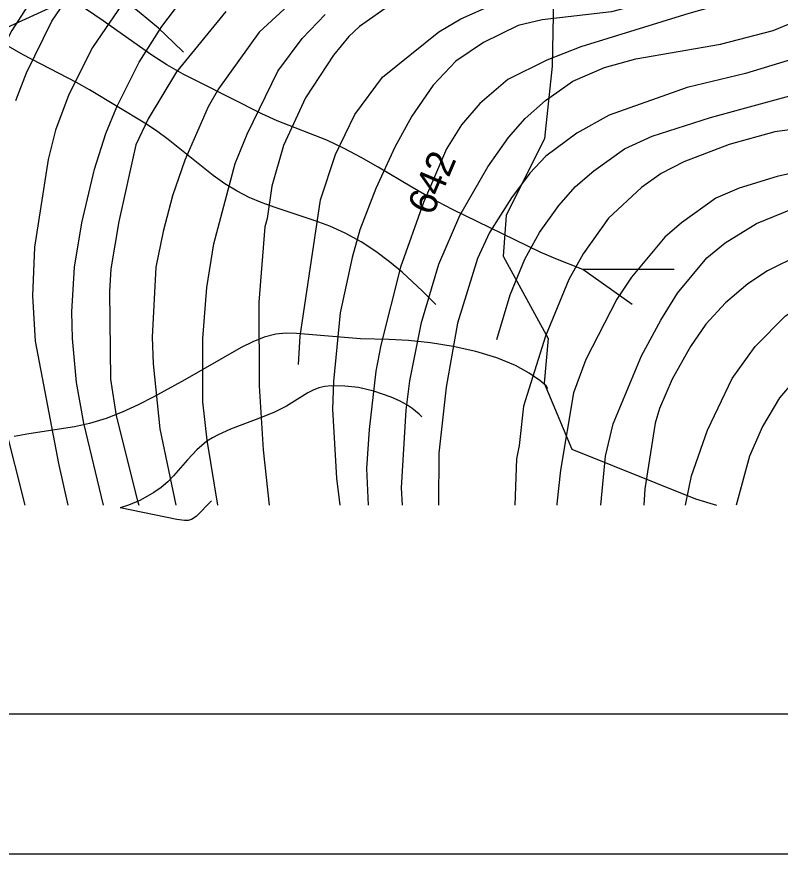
# Model space of a CAD drawing. Extents: x -709584 to -702006, y -1161789 to -1157496.
# Drawn here: x -707673.9 to -707401.6, y -1161765.5 to -1161466.8 of the extents above; entities that cross this region are included whole.
import ezdxf

# ---------------------------------------------------------------- set-up
doc = ezdxf.new("R2010")
doc.units = 0
for name, color, linetype in [('103_hranice KÚ', 7, 'Continuous'), ('120_vrstevnice hlavní', 7, 'Continuous'), ('121_vrstevnice hlavní_popis', 7, 'Continuous'), ('122_vrstevnice základní', 7, 'Continuous'), ('411_akumulovaný odtok', 7, 'Continuous'), ('800_mřížka', 7, 'Continuous')]:
    doc.layers.add(name, color=color, linetype=linetype)

msp = doc.modelspace()

# ---------------------------------------------------------------- linework, layer by layer
at = {"layer": '103_hranice KÚ'}
msp.add_lwpolyline([(-707683.31, -1161473.27), (-707622.03, -1161445.19), (-707563.2, -1161422.44), (-707517.63, -1161422.1), (-707498.37, -1161429.73), (-707482.15, -1161441.73), (-707482.92, -1161484.43), (-707485.7, -1161510.29), (-707499.41, -1161537.73), (-707500.44, -1161552.15), (-707484.44, -1161581.55), (-707485.87, -1161597.49), (-707475.98, -1161621.1), (-707431.85, -1161638.77), (-707424.36, -1161641.02)], dxfattribs=at)
at = {"layer": '120_vrstevnice hlavní'}
for points in [[(-707399.84, -1161427.58), (-707409.1, -1161436.7), (-707420.09, -1161446.39), (-707433.98, -1161454.92), (-707447.86, -1161461.43), (-707461.75, -1161465.05), (-707486.54, -1161467.97), (-707495.12, -1161469.93), (-707507.47, -1161476.05), (-707517.3, -1161482.65), (-707525.36, -1161491.22), (-707533.06, -1161502.22), (-707539.13, -1161513.36), (-707545.79, -1161528.11), (-707551.57, -1161542.87), (-707554.32, -1161552.7), (-707558.52, -1161572.38), (-707560.98, -1161596.96), (-707561.27, -1161606.8), (-707559.82, -1161631.39), (-707558.74, -1161641.02)], [(-707599.31, -1161464.9), (-707616.95, -1161486.46), (-707627.08, -1161503.24), (-707631.42, -1161512.49), (-707637.51, -1161539.86), (-707640.39, -1161556.75), (-707640.82, -1161564.85), (-707640.53, -1161596.1), (-707638.51, -1161609.11), (-707630.84, -1161639.49), (-707630.41, -1161641.02)], [(-707221.06, -1161499.47), (-707255.78, -1161518.28), (-707281.81, -1161533.18), (-707307.85, -1161545.61), (-707338.22, -1161561.09), (-707359.92, -1161570.64), (-707372.94, -1161577.44), (-707385.67, -1161585.68), (-707392.46, -1161591.76), (-707401.87, -1161602.75), (-707407.94, -1161613.02), (-707412.57, -1161623.58), (-707417.34, -1161641.02)], [(-707376.99, -1161504.25), (-707403.6, -1161507.86), (-707419.8, -1161512.35), (-707436, -1161518.57), (-707444.1, -1161522.76), (-707451.05, -1161527.68), (-707462.91, -1161538.67), (-707471.87, -1161551.4), (-707477.08, -1161560.51), (-707485.33, -1161580.76), (-707493.22, -1161605.75), (-707494.74, -1161619.69), (-707495.74, -1161624.45), (-707496.29, -1161641.02)]]:
    msp.add_lwpolyline(points, dxfattribs=at)
at = {"layer": '122_vrstevnice základní'}
for points in [[(-707674.23, -1161496.63), (-707670.46, -1161486.83), (-707661.42, -1161468.36), (-707653.65, -1161456.95), (-707635.86, -1161435.98), (-707626.76, -1161428.41), (-707610.93, -1161415.59), (-707591.72, -1161403.15), (-707559.24, -1161384.48), (-707548.25, -1161377.83), (-707535.08, -1161368.57), (-707527.42, -1161362.35), (-707515.99, -1161350.63), (-707511.51, -1161343.84), (-707506.16, -1161332.27), (-707502.39, -1161320.69), (-707501.09, -1161314.91), (-707498.06, -1161293.21), (-707490.12, -1161268.28), (-707484.77, -1161252.37), (-707480.76, -1161242.54), (-707476.24, -1161227.84), (-707475.86, -1161219.92), (-707488.36, -1161216.11)], [(-707573.71, -1161378.27), (-707622.23, -1161411.07), (-707642.2, -1161426.52), (-707658.31, -1161444.58), (-707675.64, -1161471.72), (-707687.83, -1161494.84), (-707692.46, -1161511.91), (-707696.8, -1161535.06), (-707698.39, -1161561.09), (-707698.24, -1161572.08), (-707696.8, -1161590.31), (-707694.92, -1161603.62), (-707687.58, -1161641.02)], [(-707573.42, -1161590.89), (-707572.84, -1161580.76), (-707565.6, -1161532.16), (-707560.25, -1161515.96), (-707553.31, -1161501.64), (-707543.5, -1161488.36), (-707523.37, -1161472.14), (-707515.56, -1161467.51), (-707503.99, -1161462.45), (-707492.41, -1161458.25), (-707462.04, -1161453.48), (-707455.1, -1161451.45), (-707445.26, -1161447.55), (-707438.9, -1161444.36), (-707424.87, -1161434.82), (-707414.45, -1161425.42), (-707405.48, -1161414.71), (-707399.41, -1161405.46)], [(-707396.08, -1161451.02), (-707405.92, -1161456.23), (-707416.04, -1161460.42), (-707434.27, -1161465.63), (-707472.74, -1161477.49), (-707484.89, -1161482.26), (-707498.78, -1161489.2), (-707508.76, -1161497.74), (-707515.27, -1161505.4), (-707520.62, -1161513.94)], [(-707229.59, -1161450.44), (-707240.59, -1161459.12), (-707253.17, -1161467.22), (-707267.64, -1161475.61), (-707289.04, -1161486.46), (-707304.67, -1161493.69), (-707361.66, -1161514.81), (-707373.23, -1161517.84), (-707382.48, -1161519.29), (-707402.73, -1161523.77), (-707416.33, -1161527.97), (-707424.58, -1161531.58), (-707436.87, -1161540.26), (-707442.8, -1161545.47), (-707454.66, -1161559.65), (-707459.87, -1161567.6), (-707471.01, -1161589.01), (-707475.35, -1161601.01), (-707479.98, -1161628.5), (-707481.28, -1161640.5), (-707481.26, -1161641.02)], [(-707571.1, -1161457.09), (-707587.4, -1161472.28), (-707601.91, -1161492.53), (-707605.67, -1161498.9), (-707613.92, -1161517.99), (-707618.4, -1161530.72), (-707621.73, -1161543.45), (-707624.33, -1161556.17), (-707625.63, -1161581.05), (-707625.2, -1161590.6), (-707622.88, -1161613.74), (-707617.2, -1161641.02)], [(-707634.74, -1161459.99), (-707646.89, -1161477.78), (-707655.28, -1161494.56), (-707660.06, -1161507.28), (-707662.66, -1161517.7), (-707667.58, -1161548.94), (-707668.3, -1161566.3), (-707667.29, -1161582.5), (-707659.04, -1161626.18), (-707655.69, -1161641.02)], [(-707642.99, -1161641.02), (-707649.93, -1161611.72), (-707652.54, -1161597.25), (-707653.98, -1161581.63), (-707654.27, -1161572.08), (-707653.26, -1161556.17), (-707650.66, -1161540.26), (-707646.17, -1161521.17), (-707642.12, -1161508.44), (-707638.22, -1161498.9), (-707630.26, -1161482.98), (-707622.16, -1161470.26), (-707615.07, -1161460.85)], [(-707540.15, -1161462.16), (-707551.72, -1161470.26), (-707555.48, -1161473.87), (-707560.98, -1161480.53), (-707570.96, -1161495.71), (-707578.77, -1161512.78), (-707582.96, -1161527.25), (-707584.55, -1161538.82), (-707585.42, -1161541.71), (-707587.59, -1161568.61), (-707587.45, -1161598.41), (-707586, -1161621.26), (-707583.83, -1161641.02)], [(-707602.14, -1161641.02), (-707605.96, -1161617.79), (-707607.55, -1161604.2), (-707607.55, -1161581.63), (-707606.1, -1161563.41), (-707603.65, -1161547.78), (-707595.98, -1161519.15), (-707591.78, -1161508.73), (-707580.79, -1161486.17), (-707572.11, -1161474.59), (-707563.87, -1161466.06)], [(-707498.49, -1161509.89), (-707492.56, -1161503.09), (-707485.33, -1161496.73), (-707475.64, -1161489.78), (-707464.35, -1161484.86), (-707453.07, -1161481.83), (-707422.98, -1161476.62), (-707404.18, -1161471.7), (-707393.19, -1161467.22)], [(-707392.46, -1161480.53), (-707414.02, -1161487.03), (-707434.85, -1161492.1), (-707462.62, -1161501.93), (-707474.19, -1161508.3), (-707485.18, -1161516.54), (-707490.97, -1161522.62), (-707497.48, -1161531.44), (-707505.29, -1161543.74), (-707509.63, -1161552.99), (-707516.71, -1161576.14), (-707520.76, -1161598.99), (-707523.37, -1161622.42), (-707523.5, -1161641.02)], [(-707502.68, -1161581.92), (-707497.91, -1161566.01), (-707492.7, -1161553.28), (-707487.5, -1161543.74), (-707480.55, -1161534.19), (-707474.62, -1161527.39), (-707468.11, -1161521.75), (-707457.12, -1161513.94), (-707447.29, -1161509.45), (-707426.46, -1161502.8), (-707388.27, -1161492.24)], [(-707536.28, -1161641.02), (-707536.68, -1161634.86), (-707535.08, -1161607.09), (-707533.78, -1161596.68), (-707529.59, -1161575.85), (-707523.37, -1161555.02), (-707515.85, -1161537.66), (-707505.87, -1161520.3), (-707498.49, -1161509.89)], [(-707520.62, -1161513.94), (-707528.86, -1161533.03), (-707537.11, -1161556.17), (-707544.05, -1161583.95), (-707545.79, -1161593.2), (-707548.25, -1161614.03), (-707549.12, -1161627.92), (-707548.53, -1161641.02)], [(-707465.55, -1161641.02), (-707463.92, -1161623.58), (-707461.17, -1161612.01), (-707451.05, -1161587.71), (-707444.25, -1161574.98), (-707438.32, -1161565.43), (-707427.76, -1161552.85), (-707421.25, -1161547.5), (-707410.11, -1161540.55), (-707397.24, -1161535.34), (-707366, -1161527.39), (-707352.11, -1161523.05), (-707327.81, -1161518.71), (-707310.45, -1161513.5)], [(-707435.44, -1161641.02), (-707433.25, -1161630.52), (-707427.61, -1161614.32), (-707418.79, -1161595.81), (-707410.55, -1161584.38), (-707399.7, -1161573.53), (-707386.1, -1161564.85), (-707369.9, -1161557.04), (-707352.11, -1161550.68), (-707341.7, -1161548.22), (-707331.28, -1161544.89)], [(-707394.64, -1161551.69), (-707406.21, -1161557.48), (-707413.15, -1161562.1), (-707421.1, -1161568.9), (-707428.19, -1161576.43), (-707433.69, -1161584.38), (-707440.2, -1161596.1), (-707444.68, -1161606.51), (-707446.27, -1161611.72), (-707449.89, -1161635.15), (-707450.32, -1161641.02)], [(-707670.91, -1161641.02), (-707678.14, -1161612.3)]]:
    msp.add_lwpolyline(points, dxfattribs=at)
at = {"layer": '411_akumulovaný odtok'}
for p in [(-707439.49, -1161557), (-707454.49, -1161569.5)]:
    msp.add_line(p, (-707471.99, -1161557), dxfattribs=at)
for points in [[(-707614.49, -1161479.5), (-707617.97, -1161475.96), (-707623.36, -1161470.93), (-707630.22, -1161465.15), (-707634.09, -1161462.24), (-707641.68, -1161457.12), (-707663.95, -1161443.99), (-707669.95, -1161440), (-707672.81, -1161437.88), (-707675.54, -1161435.62)], [(-707471.99, -1161557), (-707481.7, -1161553.12), (-707487.19, -1161550.74), (-707518.56, -1161535.61), (-707526.2, -1161531.56), (-707533.06, -1161527.64), (-707545.05, -1161520.46), (-707551.05, -1161517.01), (-707557.12, -1161513.78), (-707563.3, -1161510.87), (-707581.03, -1161503.89), (-707586.49, -1161501.44), (-707608.61, -1161490.31), (-707614.52, -1161487.24), (-707620.33, -1161483.96), (-707626.12, -1161480.27), (-707643.11, -1161468.28), (-707649.05, -1161464.26), (-707661.19, -1161456.63), (-707667.35, -1161453.04), (-707673.54, -1161449.62), (-707679.75, -1161446.42)], [(-707524.49, -1161569.5), (-707529.15, -1161564.66), (-707536.45, -1161557.97), (-707540.96, -1161554.25), (-707545.89, -1161550.56), (-707551.1, -1161547.13), (-707556.74, -1161544.03), (-707562.3, -1161541.5), (-707567.47, -1161539.56), (-707581.76, -1161534.89), (-707586.42, -1161533.17), (-707590.97, -1161531.24), (-707595.35, -1161529.02), (-707599.69, -1161526.35), (-707603.86, -1161523.4), (-707619.95, -1161510.6), (-707624.03, -1161507.55), (-707628.2, -1161504.74), (-707647.97, -1161492.93), (-707652.6, -1161490.31), (-707671.67, -1161480.35), (-707681.06, -1161475.1)], [(-707484.49, -1161599.5), (-707485.13, -1161598.5), (-707487.4, -1161596.5), (-707491.11, -1161593.91), (-707496.1, -1161591.15), (-707502.69, -1161588.43), (-707510.2, -1161586.16), (-707518.24, -1161584.37), (-707526.38, -1161583.08), (-707534.17, -1161582.26), (-707541.2, -1161581.9), (-707551.32, -1161581.69), (-707574.12, -1161579.75), (-707577.87, -1161579.7), (-707581.55, -1161580.06), (-707585.65, -1161581.13), (-707589.75, -1161582.77), (-707593.87, -1161584.81), (-707614, -1161596.31), (-707625.03, -1161602.41), (-707630.64, -1161605.25), (-707636.32, -1161607.86), (-707642.07, -1161610.13), (-707647.91, -1161611.94), (-707653.3, -1161613.12), (-707669.55, -1161615.53), (-707674.83, -1161616.56)], [(-707529.49, -1161609.5), (-707530.37, -1161608.54), (-707532.99, -1161606.41), (-707534.85, -1161605.18), (-707537.46, -1161603.75), (-707540.38, -1161602.44), (-707546.53, -1161600.34), (-707552.07, -1161599.11), (-707556.95, -1161598.53), (-707561.72, -1161598.42), (-707564.01, -1161598.66), (-707566.23, -1161599.18), (-707568.2, -1161599.96), (-707570.11, -1161600.96), (-707577.72, -1161605.7), (-707581.96, -1161607.81), (-707586.4, -1161609.66), (-707597.68, -1161613.96), (-707602.03, -1161615.89), (-707604.11, -1161616.99), (-707606.07, -1161618.24), (-707609.73, -1161621.34), (-707613.05, -1161624.91), (-707617.98, -1161630.6), (-707620.07, -1161632.66), (-707622.43, -1161634.69), (-707625, -1161636.56), (-707629.8, -1161639.26), (-707634, -1161641.05), (-707636.99, -1161642)], [(-707604.49, -1161639.5), (-707609.96, -1161645.09), (-707611.58, -1161646.18), (-707612.79, -1161646.52), (-707614.09, -1161646.52), (-707616.82, -1161646.12), (-707636.99, -1161642)]]:
    msp.add_lwpolyline(points, dxfattribs=at)
at = {"layer": '800_mřížka'}
for points in [[(-702006.48, -1161765.53), (-709584.12, -1161765.53), (-709584.12, -1157496.46), (-702006.48, -1157496.46)], [(-702056.48, -1161715.53), (-709534.12, -1161715.53), (-709534.12, -1157546.46), (-702056.48, -1157546.46)]]:
    msp.add_lwpolyline(points, close=True, dxfattribs=at)

# ---------------------------------------------------------------- texts
at = {"layer": '121_vrstevnice hlavní_popis'}
msp.add_text('642', height=10, rotation=66.9662, dxfattribs=at).set_placement((-707525.7, -1161538.16))

doc.saveas('drawing.dxf')
